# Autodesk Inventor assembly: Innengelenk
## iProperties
Created: 2005-01
Part Number: Innengelenk
Document SubType Name: Assembly
Designer: Administrator
Manufacturer: Standard
Standards Organization: Custom
Author: Administrator
